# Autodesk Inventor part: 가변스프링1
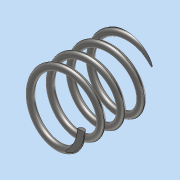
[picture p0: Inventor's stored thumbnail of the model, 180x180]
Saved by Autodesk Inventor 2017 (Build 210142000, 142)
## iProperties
Part Number: 가변스프링1
Material: 스테인레스 스틸
Document SubType Name: Modeling
Designer: MRC
Density: 8 g/cm^3
Appearance: 반연마
Mass: 5.2802 g
Surface Area: 13.6306 cm^2
Volume: 0.660025 cm^3
Author: MRC
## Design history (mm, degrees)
sketch "스케치1"
  geometry: L1 (0, 0)-(0, 22.5); L2 (0, 22.5)-(9, 22.5); L3 (0, 0)-(9, 0); C1 r 1 at (9, 0)
  constraints: 6 end point, 1 centre point, 1 coincident, 1 parallel, 1 perpendicular, 1 vertical
  dimensions: "d0" = 22.5 distance of L1.start L1.end (derived); "d1" = 9 distance of L1.end L2.end; "d2" = 9 distance of L1.start L3.end; "d3" = 2 diameter of C1
feature "코일1" sketch "스케치1" pitch "d4" = 10; turns "d6" = 5; dims "d5" = 30, "d7" = 0, angle "d8" = 90 deg, angle "d9" = 90 deg, "d10" = 0, "d11" = 0
sketch "스케치2"
  geometry: L1 (22.5, 15.094)-(0, 15.094); L2 (0, 15.094)-(0, -15.094); L3 (0, -15.094)-(22.5, -15.094); L4 (22.5, -15.094)-(22.5, 15.094); 3 further points
  constraints: 8 end point, 2 midpoint, 2 parallel, 1 coincident, 1 horizontal, 1 horizontal alignment, 1 perpendicular
  dimensions: "d12" = 22.5 distance of L2.end L3.end (= d0); "d13" = 30.18785 distance of L3.end L1.start
extrude "돌출1" sketch "스케치2" stored distance "d14" = 0; taper "d15" = 0 deg
node "솔리드1"
